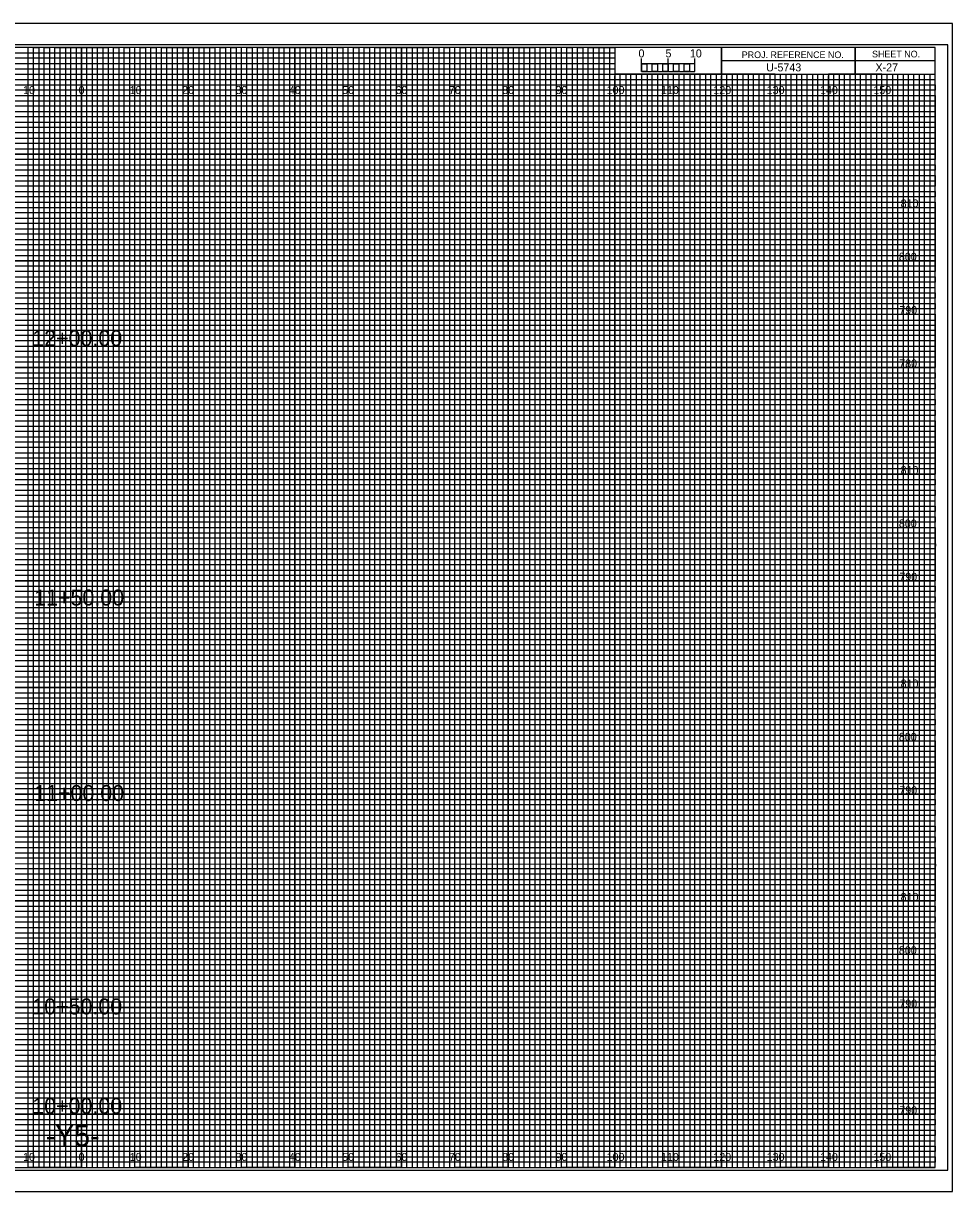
# Model space of a CAD drawing. Extents: x -13 to 323, y -4 to 214.
# Drawn here: x 149.1 to 323.3, y -4.5 to 214.5 of the extents above; entities that cross this region are included whole.
import ezdxf

# ---------------------------------------------------------------- set-up
doc = ezdxf.new("R2010")
doc.units = 0
for name, color, linetype in [('Exist Cross Section Cell', 7, 'Continuous'), ('Exist XS Center Line Elevation Label', 7, 'Continuous'), ('Exist XS Ground Line', 7, 'Continuous'), ('Prop CMT Pvmt Course 1', 7, 'Continuous'), ('Prop CMT Pvmt Course 2', 7, 'Continuous'), ('Prop CMT Pvmt Course 3', 7, 'Continuous'), ('Prop CMT Pvmt Surface', 7, 'Continuous'), ('Prop CMT Pvmt Surface Shoulder', 7, 'Continuous'), ('Prop CMT Shld Paved Course 1', 7, 'Continuous'), ('Prop CMT Shld Paved Course 2', 7, 'Continuous'), ('Prop CMT Shld Paved Course 3', 7, 'Continuous'), ('Prop CMT Slope Grass', 7, 'Continuous'), ('Prop CMT Subgrade Earthwork', 7, 'Continuous'), ('Prop XS SE Text', 7, 'Continuous'), ('Prop XS Side Slope Text', 7, 'Continuous'), ('Scratch_Level_4', 7, 'Continuous'), ('Scratch_Level_7', 7, 'Continuous')]:
    doc.layers.add(name, color=color, linetype=linetype)

msp = doc.modelspace()

# ---------------------------------------------------------------- linework, layer by layer
at = {"layer": 'Exist XS Center Line Elevation Label'}
for points in [[(145, 0), (155, 0), (155, 210), (165, 210), (165, 0), (175, 0), (175, 210), (185, 210), (185, 0), (195, 0), (195, 210), (205, 210), (205, 0), (215, 0), (215, 210), (225, 210), (225, 0), (235, 0), (235, 210), (245, 210), (245, 0), (255, 0), (255, 210), (259.93, 210), (260, 210), (260, 205), (264.99, 205), (264.99, 0), (275, 0), (275, 205), (285, 205), (285, 0), (295, 0), (295, 205), (305, 205), (305, 0), (315, 0), (315, 205)], [(0, 205), (275, 205)], [(0, 185), (320, 185), (320, 195), (0, 195)], [(0, 165), (320, 165), (320, 175), (0, 175)], [(0, 145), (320, 145), (320, 155), (0, 155)], [(0, 125), (320, 125), (320, 135), (0, 135)], [(0, 105), (320, 105), (320, 115), (0, 115)], [(0, 85), (320, 85), (320, 95), (0, 95)], [(0, 65), (320, 65), (320, 75), (0, 75)], [(0, 45), (320, 45), (320, 55), (0, 55)], [(0, 25), (320, 25), (320, 35), (0, 35)], [(0, 5), (320, 5), (320, 15), (0, 15)]]:
    msp.add_lwpolyline(points, dxfattribs=at)
at = {"layer": 'Exist XS Ground Line'}
for p, q in [((150, 210), (140, 210)), ((150, 0), (150, 210)), ((170, 210), (160, 210)), ((160, 210), (160, 0)), ((170, 0), (170, 210)), ((190, 210), (180, 210)), ((180, 210), (180, 0)), ((190, 0), (190, 210)), ((210, 210), (200, 210)), ((200, 210), (200, 0)), ((210, 0), (210, 210)), ((230, 210), (220, 210)), ((220, 210), (220, 0)), ((230, 0), (230, 210)), ((250, 210), (240, 210)), ((240, 210), (240, 0)), ((250, 0), (250, 210)), ((260, 210), (260, 0)), ((270, 0), (270, 205)), ((290, 205), (280, 205)), ((280, 205), (280, 0)), ((290, 0), (290, 205)), ((310, 205), (300, 205)), ((300, 205), (300, 0)), ((310, 0), (310, 205)), ((160, 0), (150, 0)), ((180, 0), (170, 0)), ((200, 0), (190, 0)), ((220, 0), (210, 0)), ((240, 0), (230, 0)), ((260, 0), (250, 0)), ((280, 0), (270, 0)), ((300, 0), (290, 0)), ((320, 0), (310, 0)), ((320, 0), (320, 0))]:
    msp.add_line(p, q, dxfattribs=at)
for points in [[(0, 200), (320, 200), (320, 190), (0, 190)], [(0, 180), (320, 180), (320, 170), (0, 170)], [(0, 160), (320, 160), (320, 150), (0, 150)], [(0, 140), (320, 140), (320, 130), (0, 130)], [(0, 120), (320, 120), (320, 110), (0, 110)], [(0, 100), (320, 100), (320, 90), (0, 90)], [(0, 80), (320, 80), (320, 70), (0, 70)], [(0, 60), (320, 60), (320, 50), (0, 50)], [(0, 40), (320, 40), (320, 30), (0, 30)], [(0, 20), (320, 20), (320, 10), (0, 10)]]:
    msp.add_lwpolyline(points, dxfattribs=at)
at = {"layer": 'Prop CMT Pvmt Course 2'}
msp.add_lwpolyline([(-10.8, -0.5), (322.4, -0.5), (322.4, 210.5), (-10.8, 210.5)], close=True, dxfattribs=at)
at = {"layer": 'Prop CMT Pvmt Course 3'}
for p, q in [((150, 0), (150, 210)), ((160, 0), (160, 210)), ((170, 0), (170, 210)), ((180, 0), (180, 210)), ((190, 0), (190, 210)), ((200, 0), (200, 210)), ((210, 0), (210, 210)), ((220, 0), (220, 210)), ((230, 0), (230, 210)), ((240, 0), (240, 210)), ((250, 0), (250, 210)), ((260, 0), (260, 204.69)), ((270, 0), (270, 204.69)), ((280, 0), (280, 204.69)), ((290, 0), (290, 204.69)), ((300, 0), (300, 204.69)), ((310, 0), (310, 204.69)), ((0, 200), (320, 200)), ((0, 190), (320, 190)), ((0, 180), (320, 180)), ((0, 170), (320, 170)), ((0, 160), (320, 160)), ((0, 150), (320, 150)), ((0, 140), (320, 140)), ((0, 130), (320, 130)), ((0, 120), (320, 120)), ((0, 110), (320, 110)), ((0, 100), (320, 100)), ((0, 90), (320, 90)), ((0, 80), (320, 80)), ((0, 70), (320, 70)), ((0, 60), (320, 60)), ((0, 50), (320, 50)), ((0, 40), (320, 40)), ((0, 30), (320, 30)), ((0, 20), (320, 20)), ((0, 10), (320, 10))]:
    msp.add_line(p, q, dxfattribs=at)
at = {"layer": 'Prop CMT Shld Paved Course 1'}
for p, q in [((267, 205), (266.01, 205)), ((266.01, 205), (266.01, 0)), ((267, 0), (267, 205)), ((269, 205), (268, 205)), ((268, 205), (268, 0)), ((269, 0), (269, 205)), ((266.01, 0), (265, 0)), ((268, 0), (267, 0))]:
    msp.add_line(p, q, dxfattribs=at)
for points in [[(150, 0), (151, 0), (151, 210), (152, 210), (152, 0)], [(152, 0), (153, 0), (153, 210), (154, 210), (154, 0)], [(155, 0), (156, 0), (156, 210), (157, 210), (157, 0)], [(157, 0), (158, 0), (158, 210), (159, 210), (159, 0)], [(160, 0), (161, 0), (161, 210), (162, 210), (162, 0)], [(162, 0), (163, 0), (163, 210), (164, 210), (164, 0)], [(165, 0), (166, 0), (166, 210), (167, 210), (167, 0)], [(167, 0), (168, 0), (168, 210), (169, 210), (169, 0)], [(170, 0), (171, 0), (171, 210), (172, 210), (172, 0)], [(172, 0), (173, 0), (173, 210), (174, 210), (174, 0)], [(175, 0), (176, 0), (176, 210), (177, 210), (177, 0)], [(177, 0), (178, 0), (178, 210), (179, 210), (179, 0)], [(180, 0), (181, 0), (181, 210), (182, 210), (182, 0)], [(182, 0), (183, 0), (183, 210), (184, 210), (184, 0)], [(185, 0), (186, 0), (186, 210), (187, 210), (187, 0)], [(187, 0), (188, 0), (188, 210), (189, 210), (189, 0)], [(190, 0), (191, 0), (191, 210), (192, 210), (192, 0)], [(192, 0), (193, 0), (193, 210), (194, 210), (194, 0)], [(195, 0), (196, 0), (196, 210), (197, 210), (197, 0)], [(197, 0), (198, 0), (198, 210), (199, 210), (199, 0)], [(200, 0), (201, 0), (201, 210), (202, 210), (202, 0)], [(202, 0), (203, 0), (203, 210), (204, 210), (204, 0)], [(205, 0), (206, 0), (206, 210), (207, 210), (207, 0)], [(207, 0), (208, 0), (208, 210), (209, 210), (209, 0)], [(210, 0), (211, 0), (211, 210), (212, 210), (212, 0)], [(212, 0), (213, 0), (213, 210), (214, 210), (214, 0)], [(215, 0), (216, 0), (216, 210), (217, 210), (217, 0)], [(217, 0), (218, 0), (218, 210), (219, 210), (219, 0)], [(220, 0), (221, 0), (221, 210), (222, 210), (222, 0)], [(222, 0), (223, 0), (223, 210), (224, 210), (224, 0)], [(225, 0), (226, 0), (226, 210), (227, 210), (227, 0)], [(227, 0), (228, 0), (228, 210), (229, 210), (229, 0)], [(230, 0), (231, 0), (231, 210), (232, 210), (232, 0)], [(232, 0), (233, 0), (233, 210), (234, 210), (234, 0)], [(235, 0), (236, 0), (236, 210), (237, 210), (237, 0)], [(237, 0), (238, 0), (238, 210), (239, 210), (239, 0)], [(240, 0), (241, 0), (241, 210), (242, 210), (242, 0)], [(242, 0), (243, 0), (243, 210), (244, 210), (244, 0)], [(245, 0), (246, 0), (246, 210), (247, 210), (247, 0)], [(247, 0), (248, 0), (248, 210), (249, 210), (249, 0)], [(250, 0), (251, 0), (251, 210), (252, 210), (252, 0)], [(252, 0), (253, 0), (253, 210), (254, 210), (254, 0)], [(255, 0), (256, 0), (256, 210), (257, 210), (257, 0)], [(257, 0), (258, 0), (258, 210), (259, 210), (259, 0)], [(260, 0), (261, 0), (261, 205), (262.02, 205), (262.02, 0)], [(262, 0), (263, 0), (263, 205), (263.99, 205), (263.99, 0)], [(270, 0), (270.98, 0), (270.98, 205), (272, 205), (272, 0)], [(272, 0), (273, 0), (273, 205), (274.05, 205), (274.05, 0)], [(275, 0), (276, 0), (276, 205), (277, 205), (277, 0)], [(277, 0), (278, 0), (278, 205), (279, 205), (279, 0)], [(280, 0), (281, 0), (281, 205), (282, 205), (282, 0)], [(282, 0), (283, 0), (283, 205), (284, 205), (284, 0)], [(285, 0), (286, 0), (286, 205), (287, 205), (287, 0)], [(287, 0), (288, 0), (288, 205), (289, 205), (289, 0)], [(290, 0), (291, 0), (291, 205), (292, 205), (292, 0)], [(292, 0), (293, 0), (293, 205), (294, 205), (294, 0)], [(295, 0), (296, 0), (296, 205), (297, 205), (297, 0)], [(297, 0), (298, 0), (298, 205), (299, 205), (299, 0)], [(300, 0), (301, 0), (301, 205), (302, 205), (302, 0)], [(302, 0), (303, 0), (303, 205), (304, 205), (304, 0)], [(305, 0), (306, 0), (306, 205), (307, 205), (307, 0)], [(307, 0), (308, 0), (308, 205), (309, 205), (309, 0)], [(310, 0), (311, 0), (311, 205), (312, 205), (312, 0)], [(312, 0), (313, 0), (313, 205), (314, 205), (314, 0)], [(315, 0), (316, 0), (316, 205), (317, 205), (317, 0)], [(317, 0), (318, 0), (318, 205), (319, 205), (319, 0)]]:
    msp.add_lwpolyline(points, dxfattribs=at)
at = {"layer": 'Prop CMT Shld Paved Course 2'}
for p, q in [((265, 205.49), (265, 207.9)), ((265, 206.9), (265, 207.9)), ((270, 205.49), (270, 207.9)), ((275, 205.49), (275, 207.9)), ((275, 206.9), (275, 207.9))]:
    msp.add_line(p, q, dxfattribs=at)
for points in [[(275, 206.9), (265, 206.9), (265, 205.49), (275, 205.49)], [(265, 206.9), (266, 206.9), (266, 205.49), (265, 205.49)], [(267, 206.9), (268, 206.9), (268, 205.49), (267, 205.49)], [(269, 206.9), (270, 206.9), (270, 205.49), (269, 205.49)], [(271, 206.9), (272, 206.9), (272, 205.49), (271, 205.49)], [(273, 206.9), (274, 206.9), (274, 205.49), (273, 205.49)]]:
    msp.add_lwpolyline(points, close=True, dxfattribs=at)
at = {"layer": 'Prop CMT Shld Paved Course 3'}
msp.add_lwpolyline([(-13.4, -4.5), (323.3, -4.5), (323.3, 214.5), (-13.4, 214.5)], close=True, dxfattribs=at)
at = {"layer": 'Prop CMT Subgrade Earthwork'}
for p, q in [((323.3, 214.5), (-13.4, 214.5)), ((-13.4, -4.5), (323.3, -4.5))]:
    msp.add_line(p, q, dxfattribs=at)
at = {"layer": 'Scratch_Level_4'}
for p, q in [((0, 209), (260, 209)), ((260, 209), (260, 207.98)), ((260, 207.98), (0, 207.98)), ((0, 207), (260, 207)), ((260, 205.89), (0, 205.89)), ((260, 207), (260, 205.89)), ((0, 204), (320, 204))]:
    msp.add_line(p, q, dxfattribs=at)
for points in [[(0, 203), (270, 203), (320, 203), (320, 202), (0, 202)], [(0, 201), (320, 201), (320, 199), (0, 199)], [(0, 198), (320, 198), (320, 197), (0, 196.98)], [(0, 196), (320, 196), (320, 194), (0, 194)], [(0, 193), (320, 193), (320, 192), (0, 192)], [(0, 191), (320, 191), (320, 189), (0, 189)], [(0, 188), (320, 188), (320, 187), (0, 187)], [(0, 186), (320, 186), (320, 184), (0, 184)], [(0, 183), (320, 183), (320, 182), (0, 182)], [(0, 181), (320, 181), (320, 179), (0, 179)], [(0, 178), (320, 178), (320, 177), (0, 177)], [(0, 176), (320, 176), (320, 173.95), (320, 173), (320, 172), (0, 172)], [(0, 174), (320, 174), (320, 173), (0, 173)], [(0, 171), (320, 171), (320, 169), (0, 169.03)], [(0, 169.03), (320, 169), (320, 168), (0, 168)], [(0, 167), (320, 167), (320, 166), (0, 166)], [(0, 164), (320, 164), (320, 163), (0, 163)], [(0, 162), (320, 162), (320, 161), (0, 161)], [(-0.07, 158.89), (320, 158.89), (320, 157.88), (-0.07, 157.88)], [(0, 157), (320, 157), (320, 156), (0, 156)], [(0, 154), (320, 154), (320, 153), (0, 153)], [(0, 152), (320, 152), (320, 151), (0, 151)], [(0, 149), (320, 149), (320, 148), (0, 148)], [(0, 147), (320, 147), (320, 146), (0, 146)], [(0, 144), (320, 144), (320, 143), (0, 143)], [(0, 142), (320, 142), (320, 141), (0, 141)], [(0, 139), (320, 139), (319.99, 137.98), (0, 138)], [(0, 137), (320, 137), (320, 136), (0, 136)], [(0, 134), (320, 134), (320, 133), (0, 133)], [(0, 132), (320, 132), (320, 131), (0, 131)], [(0, 129), (320, 129), (320, 128), (0, 128)], [(0, 127), (320, 127), (320, 126), (0, 126)], [(0, 124), (320, 124), (320, 123), (0, 123)], [(0, 122), (320, 122), (320, 121), (0, 121)], [(0, 119), (320, 119), (320, 118), (0, 118)], [(0, 116.99), (320.07, 116.91), (320, 116), (0, 116)], [(0, 114), (320, 114), (320, 113), (0, 113)], [(0, 112), (320, 112), (320, 111), (0, 111)], [(0, 109), (320, 109), (320, 108), (0, 108)], [(0, 107), (320, 107), (320, 106), (0, 106)], [(0, 104), (320, 104), (320, 103), (0, 103)], [(0, 102), (320, 102), (320, 101), (0, 101)], [(0, 99), (320, 99), (320, 98), (0, 98)], [(0, 97), (320, 97), (320, 96), (0, 96)], [(0, 94), (320, 94), (320, 93), (0, 93)], [(0, 92), (320, 92), (320, 91), (0, 91)], [(0, 89), (320, 89), (320, 88), (0, 88)], [(0, 87), (320, 87), (320, 86), (0, 86)], [(0, 84), (320, 84), (320, 83), (0, 83)], [(0, 82), (320, 82), (320, 81), (0, 81)], [(0, 79), (320, 79), (319.99, 77.98), (0, 78)], [(0, 77), (320, 77), (320, 76), (0, 76)], [(0, 74), (320, 74), (320, 73), (0, 73)], [(0, 72), (320, 72), (320, 71), (0, 71)], [(0, 69), (320, 69), (320, 68), (0, 68)], [(0, 67), (320, 67), (320, 66), (0, 66)], [(0, 64), (320, 64), (320, 63), (0, 63)], [(0, 62), (320, 62), (320, 61), (0, 61)], [(0, 59), (320, 59), (320, 58), (0, 58)], [(0, 56.99), (320.07, 56.91), (320, 56), (0, 56)], [(0, 54), (320, 54), (320, 53), (0, 53)], [(0, 52), (320, 52), (320, 51), (0, 51)], [(0, 49), (320, 49), (320, 48), (0, 48)], [(0, 47), (320, 47), (320, 46), (0, 46)], [(0, 44), (320, 44), (320, 43), (0, 43)], [(0, 42), (320, 42), (320, 41), (0, 41)], [(0, 39), (320, 39), (320, 38), (0, 38)], [(0, 37), (320, 37), (320, 36), (0, 36)], [(0, 34), (320, 34), (320, 33), (0, 33)], [(0, 32), (320, 32), (320, 31), (0, 31)], [(0, 29), (320, 29), (320, 28), (0, 28)], [(0, 27), (320, 27), (320, 26), (0, 26)], [(0, 24), (320, 24), (320, 23), (0, 23)], [(0, 22), (320, 22), (320, 21), (0, 21)], [(0, 19), (320, 19), (320, 18), (0, 18)], [(0, 17), (320, 17), (320, 16), (0, 16)], [(0, 14), (320, 14), (320, 13), (0, 13)], [(0, 12), (320, 12), (320, 11), (0, 11)], [(0, 9), (320, 9), (320, 8), (0, 8)], [(0, 7), (320, 7), (320, 6), (0, 6)], [(0, 4), (320, 4), (320, 3), (0, 3)], [(0, 2), (320, 2), (320, 1), (0, 1)]]:
    msp.add_lwpolyline(points, dxfattribs=at)
at = {"layer": 'Scratch_Level_7'}
for p, q in [((305, 210), (305, 205)), ((305, 205), (305, 210)), ((280, 207.5), (280, 205)), ((320, 207.49), (280, 207.49)), ((280, 205), (320, 205))]:
    msp.add_line(p, q, dxfattribs=at)
for points in [[(320, 210), (0, 210), (0, 0), (320, 0)], [(280, 210), (260, 210), (260, 205.03), (280, 205.03)], [(320, 210), (280, 210), (280, 205), (320, 205)]]:
    msp.add_lwpolyline(points, close=True, dxfattribs=at)

# ---------------------------------------------------------------- texts
at = {"layer": 'Exist Cross Section Cell'}
for s, p in [('10', (149.04, 201.25)), ('0', (159.45, 201.25)), ('0', (159.45, 201.25)), ('10', (169.04, 201.25)), ('20', (178.86, 201.25)), ('30', (188.86, 201.25)), ('40', (198.86, 201.25)), ('50', (208.86, 201.25)), ('60', (218.86, 201.25)), ('70', (228.86, 201.25)), ('80', (238.86, 201.25)), ('90', (248.86, 201.25)), ('100', (258.44, 201.25)), ('110', (268.62, 201.25)), ('120', (278.44, 201.25)), ('130', (288.44, 201.25)), ('140', (298.44, 201.25)), ('150', (308.44, 201.25)), ('10', (149.04, 1.25)), ('0', (159.45, 1.25)), ('0', (159.45, 1.25)), ('10', (169.04, 1.25)), ('20', (178.86, 1.25)), ('30', (188.86, 1.25)), ('40', (198.86, 1.25)), ('50', (208.86, 1.25)), ('60', (218.86, 1.25)), ('70', (228.86, 1.25)), ('80', (238.86, 1.25)), ('90', (248.86, 1.25)), ('100', (258.44, 1.25)), ('110', (268.62, 1.25)), ('120', (278.44, 1.25)), ('130', (288.44, 1.25)), ('140', (298.44, 1.25)), ('150', (308.44, 1.25))]:
    msp.add_text(s, height=1.5, dxfattribs=at).set_placement(p)
at = {"layer": 'Prop CMT Pvmt Course 1'}
msp.add_text('X-27', height=1.5, dxfattribs=at).set_placement((308.83, 205.5))
at = {"layer": 'Prop CMT Pvmt Surface'}
for s, p in [('810', (313.55, 180)), ('800', (313.22, 170)), ('790', (313.3, 160)), ('780', (313.28, 150)), ('810', (313.55, 130)), ('800', (313.22, 120)), ('790', (313.3, 110)), ('810', (313.55, 90)), ('800', (313.22, 80)), ('790', (313.3, 70)), ('810', (313.55, 50)), ('800', (313.22, 40)), ('790', (313.3, 30)), ('790', (313.3, 10))]:
    msp.add_text(s, height=1.5, dxfattribs=at).set_placement(p)
at = {"layer": 'Prop CMT Pvmt Surface Shoulder'}
for s, p in [('12+00.00', (150.77, 153.99)), ('11+50.00', (151.13, 105.37)), ('11+00.00', (151.13, 68.72)), ('10+50.00', (150.77, 28.72)), ('10+00.00', (150.77, 10.08))]:
    msp.add_text(s, height=3, dxfattribs=at).set_placement(p)
at = {"layer": 'Prop CMT Shld Paved Course 2'}
msp.add_text('0', height=1.5, dxfattribs=at).set_placement((264.41, 208.12))
at = {"layer": 'Prop CMT Slope Grass'}
msp.add_text('U-5743', height=1.5, dxfattribs=at).set_placement((288.34, 205.5))
at = {"layer": 'Prop XS SE Text'}
msp.add_text('-Y5-', height=4, dxfattribs=at).set_placement((153.27, 4))
at = {"layer": 'Prop XS Side Slope Text'}
for s, p in [('5', (269.47, 208.12)), ('10', (274.04, 208.12))]:
    msp.add_text(s, height=1.5, dxfattribs=at).set_placement(p)
at = {"layer": 'Scratch_Level_7'}
for s, p in [('PROJ. REFERENCE NO.', (283.77, 207.99)), ('SHEET NO.', (308.19, 208.12))]:
    msp.add_text(s, height=1.25, dxfattribs=at).set_placement(p)

doc.saveas('drawing.dxf')
